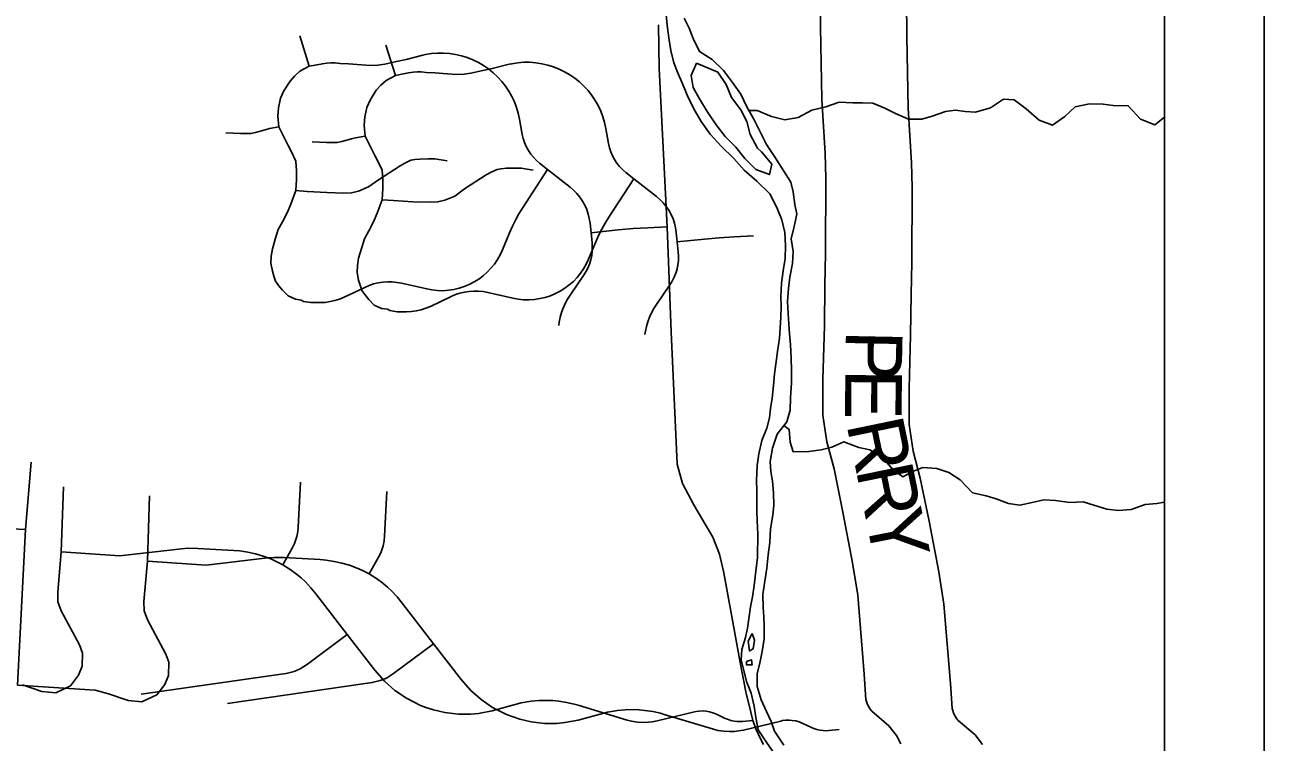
# Model space of a CAD drawing. Extents: x -38.2 to 41.9, y -4 to 24.9.
# Drawn here: x 7.758 to 9, y 19.391 to 20.109 of the extents above; entities that cross this region are included whole.
import ezdxf

# ---------------------------------------------------------------- set-up
doc = ezdxf.new("R2010")
doc.units = 0
for name, color, linetype in [('GM_X_Interchange_Ramps', 7, 'Continuous'), ('GM_X_Major_River', 7, 'Continuous'), ('GM_X_Minor_River', 7, 'Continuous'), ('GM_X_State_Location', 7, 'Continuous'), ('GM_X_State_Route', 7, 'Continuous'), ('GM_X_Township_Road', 7, 'Continuous'), ('GM_X_Township_Road_Text', 7, 'Continuous'), ('SH_Cut_Line', 7, 'Continuous'), ('SH_Data', 7, 'Continuous')]:
    doc.layers.add(name, color=color, linetype=linetype)

msp = doc.modelspace()

# ---------------------------------------------------------------- linework, layer by layer
at = {"layer": 'GM_X_Interchange_Ramps'}
for points in [[(5.6874, 16.3954), (5.9853, 16.3764), (6.413, 16.3602), (6.4263, 16.3595), (7.1336, 16.3198), (7.3442, 16.3107), (7.5793, 16.2961), (7.6901, 16.2894), (7.9696, 16.2752), (8.9, 16.2272), (8.9, 17.7063), (8.9, 17.9093), (8.9, 20.9), (5.1243, 20.9)], [(5.7739, 16.3862), (6.0718, 16.3672), (6.4995, 16.351), (6.5128, 16.3503), (7.2201, 16.3106), (7.4307, 16.3015), (7.6658, 16.2869), (7.7766, 16.2803), (8.0561, 16.266), (8.9, 16.2225), (8.9, 20.9), (5.2114, 20.9)]]:
    msp.add_lwpolyline(points, dxfattribs=at)
at = {"layer": 'GM_X_Major_River'}
for points in [[(8.4002, 20.1227), (8.4016, 20.109), (8.4031, 20.0965), (8.4052, 20.0836), (8.4082, 20.0715), (8.4119, 20.062), (8.4171, 20.0498), (8.4227, 20.0365), (8.4295, 20.0228), (8.4355, 20.0125), (8.4445, 20), (8.4557, 19.9878), (8.4682, 19.9755), (8.4787, 19.9637), (8.4915, 19.9527), (8.5046, 19.9401), (8.5114, 19.9264), (8.5166, 19.9142), (8.5195, 19.9013), (8.5202, 19.888), (8.5198, 19.8755), (8.5178, 19.863), (8.5162, 19.8505), (8.5154, 19.8372), (8.5157, 19.8274), (8.5156, 19.8164), (8.5148, 19.8058), (8.514, 19.7955), (8.512, 19.7823), (8.5104, 19.7694), (8.5092, 19.7599), (8.508, 19.7482), (8.5068, 19.7353), (8.5052, 19.7251), (8.504, 19.7156), (8.5013, 19.7054), (8.4963, 19.6929), (8.4935, 19.6797), (8.4916, 19.6679), (8.4911, 19.6528), (8.4914, 19.6433), (8.4913, 19.622), (8.4916, 19.6126), (8.4923, 19.5993), (8.4921, 19.5758), (8.4905, 19.5621), (8.4889, 19.5477), (8.487, 19.5364), (8.485, 19.5265), (8.4834, 19.5144), (8.4819, 19.5049), (8.4799, 19.4955), (8.4764, 19.4837), (8.4756, 19.4731), (8.4786, 19.4613), (8.4811, 19.4515), (8.4856, 19.4397), (8.4889, 19.4268), (8.4904, 19.4154), (8.4926, 19.4032), (8.5008, 19.391), (8.5098, 19.3781)], [(8.4284, 20.0941), (8.4236, 20.1062), (8.4187, 20.1161)], [(8.5186, 19.3879), (8.5092, 19.4016), (8.5059, 19.4115), (8.501, 19.4214), (8.4958, 19.4332), (8.4917, 19.4465), (8.4918, 19.4594), (8.4945, 19.47), (8.4968, 19.4817), (8.4988, 19.4942), (8.4989, 19.5067), (8.4986, 19.5162), (8.4979, 19.5257), (8.4976, 19.5386), (8.4996, 19.5522), (8.5015, 19.5651), (8.5028, 19.5784), (8.5043, 19.5909), (8.5052, 19.6045), (8.5075, 19.6181), (8.5084, 19.628), (8.5081, 19.6405), (8.507, 19.6523), (8.5055, 19.6618), (8.5049, 19.672), (8.5072, 19.6853), (8.5118, 19.6993), (8.5214, 19.7117), (8.5249, 19.7234), (8.5253, 19.7359), (8.5262, 19.7507), (8.5262, 19.7629), (8.5259, 19.7758), (8.5253, 19.789), (8.5242, 19.8), (8.5228, 19.8198), (8.5221, 19.8323), (8.523, 19.8452), (8.5246, 19.8565), (8.5273, 19.8702), (8.5277, 19.8823), (8.5259, 19.8952), (8.5287, 19.9073), (8.5314, 19.9198), (8.5296, 19.9293), (8.5277, 19.9422), (8.5255, 19.9517), (8.509, 19.9776), (8.5012, 19.9897), (8.4952, 20.0015), (8.4885, 20.0148), (8.4813, 20.0274), (8.4754, 20.04), (8.4671, 20.0518), (8.4581, 20.0636), (8.4468, 20.0746), (8.434, 20.0827), (8.4297, 20.0916), (8.4284, 20.0941)], [(8.4309, 20.0709), (8.4255, 20.0588), (8.4277, 20.0467), (8.4341, 20.0353), (8.4416, 20.0227), (8.4506, 20.0094), (8.4596, 19.9976), (8.4705, 19.9869), (8.4795, 19.9755), (8.4904, 19.9644), (8.504, 19.9594), (8.5063, 19.97), (8.4962, 19.9822)], [(8.4962, 19.9822), (8.4921, 19.986), (8.4846, 19.9997), (8.4813, 20.0126), (8.4753, 20.0244), (8.4659, 20.0366), (8.4607, 20.0495), (8.4524, 20.0621), (8.4309, 20.0709)], [(8.4867, 19.4996), (8.4829, 19.492), (8.484, 19.4822), (8.4878, 19.4844)], [(8.4878, 19.4844), (8.489, 19.4931), (8.4867, 19.4996)], [(8.4869, 19.4681), (8.4862, 19.4731), (8.4809, 19.4716)], [(8.4809, 19.4716), (8.4812, 19.4682), (8.4869, 19.4681)]]:
    msp.add_lwpolyline(points, dxfattribs=at)
at = {"layer": 'GM_X_Minor_River'}
for points in [[(8.4836, 20.0235), (8.4918, 20.0237), (8.5062, 20.0177), (8.5195, 20.0143), (8.5327, 20.0165), (8.5467, 20.0241), (8.5607, 20.0272), (8.574, 20.0321), (8.5876, 20.0313), (8.5974, 20.0313), (8.6076, 20.031), (8.6198, 20.026), (8.6304, 20.0207), (8.6436, 20.015), (8.6568, 20.015), (8.6671, 20.0181), (8.6807, 20.0226), (8.6905, 20.0241), (8.7004, 20.0226), (8.7106, 20.0219), (8.7257, 20.0264), (8.7386, 20.0351), (8.7492, 20.0344), (8.7613, 20.0253), (8.7745, 20.0139), (8.7878, 20.009), (8.8003, 20.0177), (8.8105, 20.0272), (8.8249, 20.0302), (8.8385, 20.0298), (8.8487, 20.0287), (8.8638, 20.0283), (8.876, 20.015), (8.8903, 20.0094), (8.9, 20.017)], [(8.5186, 19.7081), (8.5237, 19.7041), (8.5249, 19.6912), (8.5279, 19.6817), (8.5434, 19.6821), (8.5559, 19.6836), (8.5665, 19.6863), (8.5786, 19.6916), (8.5938, 19.6859), (8.6047, 19.6836), (8.6176, 19.6757), (8.6278, 19.6639), (8.6377, 19.6567), (8.6479, 19.662), (8.6577, 19.6658), (8.6717, 19.6651), (8.6838, 19.6609), (8.6952, 19.6537), (8.7077, 19.6404), (8.7213, 19.6374), (8.7312, 19.6347), (8.7436, 19.6298), (8.755, 19.6283), (8.7675, 19.6309), (8.7792, 19.6336), (8.7909, 19.6328), (8.8053, 19.6309), (8.8186, 19.6317), (8.8292, 19.6283), (8.8424, 19.6241), (8.8538, 19.623), (8.8666, 19.6237), (8.8806, 19.629), (8.8924, 19.6298), (8.9, 19.6312)]]:
    msp.add_lwpolyline(points, dxfattribs=at)
at = {"layer": 'GM_X_State_Location'}
for p, q in [((8.1293, 20.0587), (8.1197, 20.0892)), ((7.7585, 19.6038), (7.7639, 19.6714)), ((7.8805, 19.5722), (7.8828, 19.6375))]:
    msp.add_line(p, q, dxfattribs=at)
for points in [[(8.7177, 19.3883), (8.7104, 19.398), (8.6931, 19.4125), (8.6914, 19.4146), (8.6888, 19.4192), (8.6872, 19.4244), (8.6855, 19.4496), (8.679, 19.5289), (8.6737, 19.5613), (8.6641, 19.6121), (8.6552, 19.6554), (8.6481, 19.6824), (8.6442, 19.7091), (8.6442, 19.7452), (8.6455, 19.7984), (8.6462, 19.8393), (8.6468, 19.8712), (8.6471, 19.9465), (8.6465, 19.9713), (8.643, 20.0258), (8.6419, 20.0979), (8.6415, 20.1353)], [(8.2432, 20.07), (8.2262, 20.0656), (8.2167, 20.0636), (8.2049, 20.0609), (8.198, 20.06), (8.1904, 20.0596), (8.1815, 20.0603), (8.1687, 20.0613), (8.1601, 20.0616), (8.1549, 20.0623), (8.1509, 20.0623), (8.147, 20.0619), (8.1424, 20.0613), (8.1371, 20.0603), (8.1293, 20.0587)], [(8.4117, 19.8919), (8.4107, 19.9015), (8.41, 19.9061), (8.4089, 19.9107), (8.4074, 19.9152), (8.4055, 19.9195), (8.4032, 19.9236), (8.4006, 19.9275), (8.3976, 19.9312), (8.3943, 19.9346), (8.3907, 19.9376), (8.3682, 19.9553), (8.3602, 19.9616), (8.3569, 19.9644), (8.3539, 19.9675), (8.3512, 19.9709), (8.3488, 19.9744), (8.3468, 19.9782), (8.3451, 19.9822), (8.3438, 19.9863), (8.3428, 19.9905), (8.3401, 20.0057), (8.3388, 20.0116), (8.3371, 20.0174), (8.3349, 20.0231), (8.3323, 20.0285), (8.3293, 20.0338), (8.3259, 20.0388), (8.3222, 20.0436), (8.3181, 20.0481), (8.3137, 20.0522), (8.309, 20.056), (8.304, 20.0594), (8.2987, 20.0625), (8.2933, 20.0651), (8.2876, 20.0674), (8.2819, 20.0692), (8.276, 20.0705), (8.27, 20.0714), (8.2639, 20.0719), (8.2579, 20.0719), (8.2518, 20.0714), (8.2458, 20.0705), (8.2432, 20.07)], [(8.1211, 19.8245), (8.1153, 19.8253), (8.1079, 19.8286), (8.1026, 19.8343), (8.0985, 19.8392), (8.0956, 19.8434), (8.094, 19.8475), (8.0923, 19.8536), (8.0907, 19.8614), (8.0911, 19.8684), (8.0923, 19.8758), (8.0956, 19.8865), (8.0981, 19.8951), (8.1026, 19.903), (8.1071, 19.912), (8.1108, 19.9206), (8.1158, 19.9342), (8.1166, 19.9453), (8.1166, 19.9539), (8.1158, 19.9638), (8.1112, 19.9736), (8.1084, 19.9786), (8.1042, 19.9872), (8.0989, 19.9979), (8.0977, 20.0086), (8.0985, 20.0172), (8.1005, 20.0267), (8.1038, 20.0341), (8.11, 20.0439), (8.1145, 20.0489), (8.1199, 20.0538), (8.1293, 20.0587)], [(8.0457, 19.9921), (8.0602, 19.9915), (8.0707, 19.9915), (8.0755, 19.9925), (8.0852, 19.9953), (8.0893, 19.9963), (8.0989, 19.9979)], [(8.1158, 19.9342), (8.1273, 19.9335), (8.1467, 19.9322), (8.164, 19.9317), (8.1717, 19.932), (8.1786, 19.9337), (8.1887, 19.9379), (8.1985, 19.945), (8.2202, 19.9591), (8.2259, 19.9621), (8.2311, 19.9645), (8.235, 19.9653), (8.2402, 19.9658), (8.2483, 19.966), (8.2553, 19.966), (8.2673, 19.964)], [(8.1403, 19.822), (8.1452, 19.8222), (8.1501, 19.8229), (8.1549, 19.824), (8.1596, 19.8255), (8.1642, 19.8274), (8.1849, 19.8373), (8.1893, 19.8391), (8.1938, 19.8406), (8.1983, 19.8417), (8.203, 19.8424), (8.2077, 19.8427), (8.2125, 19.8426), (8.2172, 19.8422), (8.2218, 19.8413), (8.2469, 19.8356), (8.2523, 19.8346), (8.2577, 19.834), (8.2632, 19.834), (8.2686, 19.8343), (8.274, 19.8351), (8.2794, 19.8363), (8.2845, 19.838), (8.2896, 19.8401), (8.2944, 19.8426), (8.2991, 19.8455), (8.3034, 19.8488), (8.3075, 19.8524), (8.3113, 19.8563), (8.3148, 19.8606), (8.3178, 19.8651), (8.3205, 19.8698), (8.3228, 19.8748), (8.33, 19.8921), (8.3328, 19.8984), (8.336, 19.9047), (8.3394, 19.9108), (8.343, 19.9167), (8.3682, 19.9553)], [(8.3793, 19.7991), (8.3799, 19.8024), (8.3809, 19.8072), (8.3822, 19.8119), (8.3838, 19.8165), (8.3858, 19.821), (8.3881, 19.8253), (8.3908, 19.8294), (8.4043, 19.849), (8.4066, 19.8527), (8.4086, 19.8566), (8.4102, 19.8606), (8.4115, 19.8648), (8.4124, 19.8691), (8.4129, 19.8734), (8.413, 19.8778), (8.4127, 19.8821), (8.4117, 19.8919)], [(8.4117, 19.8919), (8.4389, 19.8948), (8.4537, 19.8961), (8.4686, 19.8969), (8.488, 19.898)], [(8.1211, 19.8245), (8.1236, 19.8232), (8.131, 19.822), (8.1403, 19.822)], [(8.1204, 19.6419), (8.1182, 19.597), (8.1178, 19.5925), (8.1168, 19.5876), (8.1144, 19.5805), (8.1122, 19.576), (8.1029, 19.5593)], [(7.7232, 19.6055), (7.7585, 19.6038), (7.7504, 19.4479), (7.8283, 19.4429), (7.8417, 19.4391), (7.8613, 19.4324), (7.8751, 19.4311), (7.8899, 19.4381), (7.898, 19.4486), (7.9017, 19.4577), (7.902, 19.4708), (7.899, 19.4789), (7.8805, 19.5133), (7.8774, 19.5223), (7.8771, 19.5318), (7.8805, 19.5722), (7.9395, 19.5682), (8.001, 19.5753), (8.0075, 19.5758), (8.0175, 19.5758), (8.0537, 19.5736), (8.0598, 19.5731), (8.0677, 19.5719), (8.0755, 19.5702), (8.0832, 19.568), (8.0907, 19.5652), (8.0961, 19.5627), (8.1029, 19.5593), (8.1101, 19.5547), (8.1165, 19.55), (8.1211, 19.5462), (8.1254, 19.5421), (8.1309, 19.5363), (8.136, 19.5301), (8.1672, 19.4894), (8.1951, 19.4536), (8.2048, 19.4425), (8.2152, 19.4334), (8.2266, 19.4256), (8.2406, 19.4184), (8.2462, 19.4163), (8.2537, 19.4138), (8.2652, 19.4112), (8.2731, 19.4101), (8.279, 19.4096), (8.2909, 19.4096), (8.2988, 19.4103), (8.3124, 19.4128), (8.3418, 19.4209), (8.3516, 19.4225), (8.3595, 19.4232), (8.3675, 19.4234), (8.3734, 19.4232), (8.3793, 19.4226), (8.3871, 19.4214), (8.3948, 19.4197), (8.3986, 19.4186), (8.4481, 19.4037), (8.4523, 19.4026), (8.4582, 19.4017), (8.4641, 19.4013), (8.4691, 19.4015), (8.473, 19.402), (8.4779, 19.4029), (8.5154, 19.4119), (8.5172, 19.4123), (8.5201, 19.4127), (8.5241, 19.4128), (8.527, 19.4126), (8.5304, 19.4121), (8.5337, 19.4111), (8.5374, 19.4096), (8.5462, 19.4054), (8.5484, 19.4045), (8.5517, 19.4034), (8.555, 19.4027), (8.5579, 19.4023), (8.5602, 19.4022), (8.5637, 19.4024), (8.574, 19.4034)], [(7.9609, 19.4296), (8.0987, 19.4494), (8.106, 19.4504), (8.114, 19.4525), (8.1201, 19.455), (8.1273, 19.4596), (8.1672, 19.4894)]]:
    msp.add_lwpolyline(points, dxfattribs=at)
at = {"layer": 'GM_X_State_Route'}
msp.add_lwpolyline([(8.4982, 19.3883), (8.4954, 19.3933), (8.4907, 19.4033), (8.4875, 19.4126), (8.4853, 19.4207), (8.4805, 19.4413), (8.4748, 19.4704), (8.4702, 19.4963), (8.4585, 19.5604), (8.454, 19.5792), (8.4472, 19.5963), (8.4285, 19.6278), (8.417, 19.6499), (8.4117, 19.6692), (8.4057, 19.8017), (8.4015, 19.9072), (8.3935, 20.0658), (8.393, 20.1096)], dxfattribs=at)
at = {"layer": 'GM_X_Township_Road'}
for p, q in [((8.0428, 20.0679), (8.0332, 20.0984)), ((7.794, 19.5814), (7.7963, 19.6467))]:
    msp.add_line(p, q, dxfattribs=at)
for points in [[(8.6358, 19.389), (8.6313, 19.3975), (8.6239, 19.4072), (8.6067, 19.4217), (8.6049, 19.4237), (8.6023, 19.4284), (8.6007, 19.4336), (8.599, 19.4588), (8.5925, 19.5381), (8.5873, 19.5705), (8.5777, 19.6213), (8.5688, 19.6646), (8.5617, 19.6916), (8.5577, 19.7183), (8.5577, 19.7544), (8.5591, 19.8076), (8.5597, 19.8485), (8.5603, 19.8804), (8.5606, 19.9557), (8.56, 19.9805), (8.5565, 20.0349), (8.5554, 20.1071), (8.555, 20.1445)], [(8.1567, 20.0792), (8.1398, 20.0747), (8.1302, 20.0728), (8.1184, 20.0701), (8.1115, 20.0691), (8.1039, 20.0688), (8.095, 20.0695), (8.0822, 20.0705), (8.0737, 20.0708), (8.0684, 20.0715), (8.0645, 20.0715), (8.0605, 20.0711), (8.0559, 20.0705), (8.0506, 20.0695), (8.0428, 20.0679)], [(8.3252, 19.9011), (8.3242, 19.9106), (8.3235, 19.9153), (8.3224, 19.9199), (8.3209, 19.9244), (8.319, 19.9287), (8.3167, 19.9328), (8.3141, 19.9367), (8.3111, 19.9404), (8.3078, 19.9437), (8.3042, 19.9468), (8.2817, 19.9645), (8.2737, 19.9708), (8.2705, 19.9736), (8.2675, 19.9767), (8.2648, 19.98), (8.2624, 19.9836), (8.2603, 19.9874), (8.2586, 19.9914), (8.2573, 19.9955), (8.2563, 19.9997), (8.2536, 20.0149), (8.2523, 20.0208), (8.2506, 20.0266), (8.2484, 20.0322), (8.2458, 20.0377), (8.2428, 20.043), (8.2395, 20.048), (8.2357, 20.0528), (8.2316, 20.0573), (8.2272, 20.0614), (8.2225, 20.0652), (8.2175, 20.0686), (8.2123, 20.0717), (8.2068, 20.0743), (8.2012, 20.0766), (8.1954, 20.0784), (8.1895, 20.0797), (8.1835, 20.0806), (8.1774, 20.0811), (8.1714, 20.0811), (8.1653, 20.0806), (8.1593, 20.0797), (8.1567, 20.0792)], [(8.0346, 19.8336), (8.0289, 19.8345), (8.0215, 19.8378), (8.0161, 19.8435), (8.012, 19.8484), (8.0091, 19.8525), (8.0075, 19.8567), (8.0058, 19.8628), (8.0042, 19.8706), (8.0046, 19.8776), (8.0058, 19.885), (8.0091, 19.8957), (8.0116, 19.9043), (8.0161, 19.9121), (8.0206, 19.9212), (8.0243, 19.9298), (8.0293, 19.9434), (8.0301, 19.9545), (8.0301, 19.9631), (8.0293, 19.973), (8.0248, 19.9828), (8.0219, 19.9878), (8.0178, 19.9964), (8.0124, 20.0071), (8.0112, 20.0178), (8.012, 20.0264), (8.0141, 20.0359), (8.0174, 20.0433), (8.0235, 20.0531), (8.028, 20.0581), (8.0334, 20.063), (8.0428, 20.0679)], [(7.9592, 20.0013), (7.9737, 20.0007), (7.9842, 20.0007), (7.989, 20.0017), (7.9987, 20.0044), (8.0028, 20.0055), (8.0124, 20.0071)], [(8.0293, 19.9434), (8.0408, 19.9426), (8.0603, 19.9414), (8.0775, 19.9409), (8.0852, 19.9412), (8.0921, 19.9429), (8.1022, 19.9471), (8.1121, 19.9542), (8.1338, 19.9683), (8.1394, 19.9712), (8.1446, 19.9737), (8.1486, 19.9745), (8.1537, 19.9749), (8.1619, 19.9752), (8.1688, 19.9752), (8.1809, 19.9732)], [(8.0538, 19.8312), (8.0587, 19.8314), (8.0636, 19.8321), (8.0684, 19.8332), (8.0731, 19.8347), (8.0777, 19.8366), (8.0984, 19.8464), (8.1028, 19.8483), (8.1073, 19.8498), (8.1119, 19.8509), (8.1165, 19.8516), (8.1213, 19.8519), (8.126, 19.8518), (8.1307, 19.8513), (8.1353, 19.8505), (8.1605, 19.8448), (8.1658, 19.8438), (8.1713, 19.8432), (8.1767, 19.8431), (8.1822, 19.8435), (8.1876, 19.8443), (8.1929, 19.8455), (8.1981, 19.8472), (8.2031, 19.8493), (8.208, 19.8518), (8.2126, 19.8547), (8.217, 19.858), (8.2211, 19.8616), (8.2248, 19.8655), (8.2283, 19.8698), (8.2314, 19.8743), (8.2341, 19.879), (8.2364, 19.884), (8.2435, 19.9012), (8.2464, 19.9076), (8.2495, 19.9139), (8.2529, 19.92), (8.2566, 19.9259), (8.2817, 19.9645)], [(8.3252, 19.9011), (8.3525, 19.9039), (8.3673, 19.9053), (8.3821, 19.9061), (8.4015, 19.9072)], [(8.2929, 19.8083), (8.2934, 19.8116), (8.2944, 19.8164), (8.2957, 19.8211), (8.2974, 19.8257), (8.2993, 19.8302), (8.3017, 19.8345), (8.3043, 19.8386), (8.3178, 19.8582), (8.3201, 19.8619), (8.3221, 19.8658), (8.3237, 19.8698), (8.325, 19.874), (8.3259, 19.8783), (8.3264, 19.8826), (8.3265, 19.887), (8.3263, 19.8913), (8.3252, 19.9011)], [(8.0346, 19.8336), (8.0371, 19.8324), (8.0445, 19.8312), (8.0538, 19.8312)], [(8.034, 19.6511), (8.0317, 19.6062), (8.0313, 19.6017), (8.0303, 19.5968), (8.0279, 19.5897), (8.0257, 19.5852), (8.0164, 19.5685)], [(7.7552, 19.4483), (7.7748, 19.4416), (7.7886, 19.4403), (7.8034, 19.4473), (7.8115, 19.4578), (7.8152, 19.4669), (7.8155, 19.48), (7.8125, 19.4881), (7.794, 19.5224), (7.7909, 19.5315), (7.7906, 19.541), (7.794, 19.5814), (7.853, 19.5774), (7.9146, 19.5845), (7.9211, 19.585), (7.931, 19.5849), (7.9672, 19.5828), (7.9733, 19.5823), (7.9812, 19.5811), (7.989, 19.5794), (7.9967, 19.5771), (8.0042, 19.5744), (8.0097, 19.5719), (8.0164, 19.5685), (8.0236, 19.5639), (8.03, 19.5592), (8.0346, 19.5554), (8.039, 19.5513), (8.0444, 19.5455), (8.0495, 19.5393), (8.0808, 19.4986), (8.1086, 19.4628), (8.1183, 19.4517), (8.1287, 19.4426), (8.1401, 19.4348), (8.1542, 19.4276), (8.1597, 19.4255), (8.1672, 19.423), (8.1788, 19.4204), (8.1866, 19.4193), (8.1925, 19.4188), (8.2044, 19.4188), (8.2123, 19.4195), (8.226, 19.422), (8.2553, 19.43), (8.2651, 19.4317), (8.273, 19.4324), (8.281, 19.4326), (8.2869, 19.4324), (8.2928, 19.4318), (8.3007, 19.4306), (8.3084, 19.4289), (8.3122, 19.4278), (8.3616, 19.4129), (8.3658, 19.4118), (8.3717, 19.4109), (8.3776, 19.4105), (8.3826, 19.4107), (8.3865, 19.4111), (8.3914, 19.4121), (8.4289, 19.4211), (8.4307, 19.4215), (8.4336, 19.4219), (8.4376, 19.422), (8.4405, 19.4218), (8.4439, 19.4213), (8.4472, 19.4203), (8.451, 19.4188), (8.4598, 19.4146), (8.4619, 19.4137), (8.4652, 19.4126), (8.4686, 19.4119), (8.4714, 19.4115), (8.4737, 19.4114), (8.4772, 19.4116), (8.4875, 19.4126)], [(7.8744, 19.4388), (8.0122, 19.4586), (8.0195, 19.4596), (8.0275, 19.4616), (8.0336, 19.4642), (8.0409, 19.4688), (8.0808, 19.4986)]]:
    msp.add_lwpolyline(points, dxfattribs=at)
at = {"layer": 'SH_Cut_Line'}
msp.add_lwpolyline([(5.6874, 16.3954), (5.9853, 16.3764), (6.413, 16.3602), (6.4263, 16.3595), (7.1336, 16.3198), (7.3442, 16.3107), (7.5793, 16.2961), (7.6901, 16.2894), (7.9696, 16.2752), (8.9, 16.2272), (8.9, 17.7063), (8.9, 17.9093), (8.9, 20.9), (2.1103, 20.9)], dxfattribs=at)
at = {"layer": 'SH_Data'}
for p, q in [((9, 21), (9, 14)), ((8.9, 20.9), (8.9, 17.9093))]:
    msp.add_line(p, q, dxfattribs=at)

# ---------------------------------------------------------------- texts
at = {"layer": 'GM_X_Township_Road_Text'}
for s, rotation, p in [('P', 268.869, (8.5808, 19.804)), ('E', 269.6471, (8.5801, 19.7648)), ('R', 281.6809, (8.5811, 19.7096)), ('R', 281.5488, (8.5905, 19.6639)), ('Y', 281.3928, (8.5998, 19.6183))]:
    msp.add_text(s, height=0.0568, rotation=rotation, dxfattribs=at).set_placement(p)

doc.saveas('drawing.dxf')
